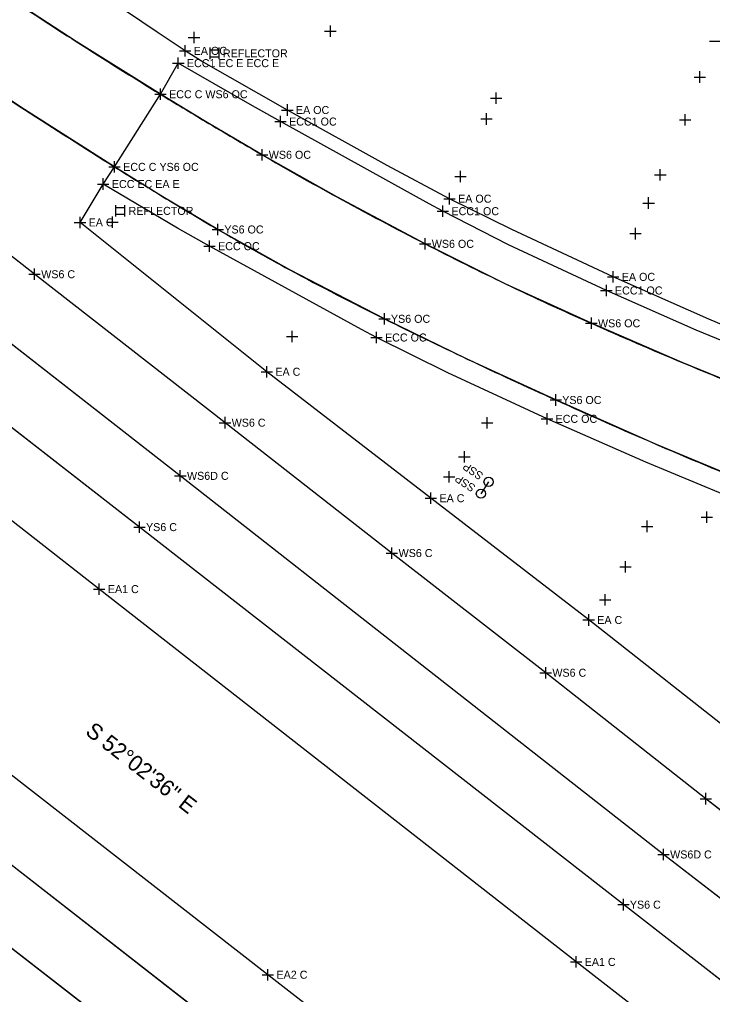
# Model space of a CAD drawing. Extents: x 1324236 to 1326110, y 459090 to 460782.
# Drawn here: x 1324542.9 to 1324664.1, y 460451 to 460621.6 of the extents above; entities that cross this region are included whole.
import ezdxf

# ---------------------------------------------------------------- set-up
doc = ezdxf.new("R2010")
doc.units = 0
for name, color, linetype in [('BD_X_Canopy', 7, 'Continuous'), ('DR_X_Ditch', 7, 'Continuous'), ('DT_X_Contour_Minor', 7, 'Continuous'), ('DT_X_Terrain_Ground_Line', 7, 'Continuous'), ('DV_X_Property_Line', 7, 'Continuous'), ('PM_X_Edge_Line', 7, 'Continuous'), ('PM_X_Lane_Line', 7, 'Continuous'), ('PV_X_Shoulder', 7, 'Continuous'), ('RW_X_CL', 7, 'Continuous'), ('RW_X_Esmt_SH', 7, 'Continuous')]:
    doc.layers.add(name, color=color, linetype=linetype)

msp = doc.modelspace()

# ---------------------------------------------------------------- linework, layer by layer
at = {"layer": 'BD_X_Canopy'}
for points in [[(1324899.46, 460285.8), (1324816.32, 460350.02), (1324738, 460411.76), (1324655.48, 460475.52), (1324571, 460541.76), (1324483.76, 460609.87), (1324398.74, 460676.2), (1324371.29, 460697.8)], [(1324658.11, 460368.1), (1324570.73, 460436.38), (1324490.36, 460498.76), (1324409.95, 460562.12), (1324331.06, 460623.37)]]:
    msp.add_lwpolyline(points, dxfattribs=at)
at = {"layer": 'DR_X_Ditch'}
for points in [[(1324878.81, 460316.8), (1324851.22, 460338.14), (1324823.13, 460360.06), (1324797.18, 460380.62), (1324771.19, 460400.89), (1324745.05, 460421.13), (1324717.74, 460442.29), (1324690.08, 460463.98), (1324662.89, 460485.28), (1324634.89, 460507.31), (1324608, 460528.25), (1324578.82, 460551.06), (1324545.51, 460577.03), (1324519.35, 460597.5), (1324491.34, 460619.11), (1324462.72, 460641.59), (1324434.69, 460663.56), (1324406.17, 460685.88), (1324379.47, 460706.64)], [(1324891.6, 460277.31), (1324809.63, 460340.84), (1324730.77, 460402.67), (1324648.48, 460466.74), (1324563.88, 460532.79), (1324477.11, 460600.29), (1324390.8, 460667.51), (1324364.85, 460687.72)], [(1324662.39, 460379.05), (1324578.69, 460444.65), (1324497.47, 460507.91), (1324417.96, 460569.9), (1324337.82, 460632.62)], [(1324672.91, 460555.83), (1324658.73, 460561.61), (1324658.73, 460561.61), (1324642.88, 460568.45), (1324642.88, 460568.45), (1324627.95, 460575.32), (1324627.95, 460575.32), (1324613.8, 460582.35), (1324613.8, 460582.35), (1324598.37, 460590.55), (1324598.37, 460590.55), (1324585.3, 460597.93), (1324585.3, 460597.93), (1324575.38, 460603.77), (1324575.38, 460603.77), (1324567.54, 460608.52), (1324567.54, 460608.52), (1324552.81, 460617.74), (1324552.81, 460617.74), (1324540.09, 460626.06)], [(1324667.15, 460541.87), (1324654.26, 460547.26), (1324654.26, 460547.26), (1324636.66, 460555.03), (1324636.66, 460555.03), (1324621.17, 460562.19), (1324621.17, 460562.19), (1324606.7, 460569.23), (1324606.7, 460569.23), (1324590.14, 460577.8), (1324590.14, 460577.8), (1324577.57, 460584.86), (1324577.57, 460584.86), (1324567.95, 460590.6), (1324567.95, 460590.6), (1324559.51, 460595.81), (1324559.51, 460595.81), (1324543.75, 460605.86), (1324543.75, 460605.86), (1324531.79, 460613.74)]]:
    msp.add_lwpolyline(points, dxfattribs=at)
at = {"layer": 'DT_X_Contour_Minor'}
msp.add_line((1324624.9, 460540.71), (1324623.56, 460538.64), dxfattribs=at)
for centre in [(1324624.9, 460540.71), (1324623.56, 460538.64)]:
    msp.add_circle(centre, 0.8, dxfattribs=at)
at = {"layer": 'DT_X_Terrain_Ground_Line'}
for p, q in [((1324576.15, 460616.68), (1324576.15, 460614.68)), ((1324577.75, 460616.68), (1324577.75, 460614.68)), ((1324576.15, 460616.28), (1324577.75, 460616.28)), ((1324576.15, 460615.08), (1324577.75, 460615.08)), ((1324559.66, 460589.12), (1324559.66, 460587.12)), ((1324559.66, 460588.72), (1324561.26, 460588.72)), ((1324561.26, 460589.12), (1324561.26, 460587.12)), ((1324559.66, 460587.52), (1324561.26, 460587.52))]:
    msp.add_line(p, q, dxfattribs=at)
at = {"layer": 'DV_X_Property_Line'}
for p, q in [((1324571.84, 460615.11), (1324571.84, 460617.11)), ((1324570.65, 460612.96), (1324570.65, 460614.96)), ((1324570.84, 460616.11), (1324572.84, 460616.11)), ((1324569.65, 460613.96), (1324571.65, 460613.96)), ((1324566.54, 460608.52), (1324568.54, 460608.52)), ((1324567.54, 460607.52), (1324567.54, 460609.52)), ((1324589.72, 460604.76), (1324589.72, 460606.76)), ((1324588.52, 460602.74), (1324588.52, 460604.74)), ((1324588.72, 460605.76), (1324590.72, 460605.76)), ((1324587.52, 460603.74), (1324589.52, 460603.74)), ((1324559.51, 460594.81), (1324559.51, 460596.81)), ((1324558.51, 460595.81), (1324560.51, 460595.81)), ((1324556.53, 460592.81), (1324558.53, 460592.81)), ((1324557.53, 460591.81), (1324557.53, 460593.81)), ((1324618.08, 460589.25), (1324618.08, 460591.25)), ((1324617.08, 460590.25), (1324619.08, 460590.25)), ((1324615.91, 460588.06), (1324617.91, 460588.06)), ((1324616.91, 460587.06), (1324616.91, 460589.06)), ((1324552.47, 460586.1), (1324554.47, 460586.1)), ((1324553.47, 460585.1), (1324553.47, 460587.1)), ((1324576.1, 460580.94), (1324576.1, 460582.94)), ((1324575.1, 460581.94), (1324577.1, 460581.94)), ((1324646.7, 460575.57), (1324646.7, 460577.57)), ((1324645.7, 460576.57), (1324647.7, 460576.57)), ((1324644.5, 460574.19), (1324646.5, 460574.19)), ((1324645.5, 460573.19), (1324645.5, 460575.19)), ((1324604.3, 460565.96), (1324606.3, 460565.96)), ((1324605.3, 460564.96), (1324605.3, 460566.96)), ((1324586.12, 460558.97), (1324586.12, 460560.97)), ((1324585.12, 460559.97), (1324587.12, 460559.97)), ((1324635.12, 460550.73), (1324635.12, 460552.73)), ((1324634.12, 460551.73), (1324636.12, 460551.73)), ((1324614.82, 460536.84), (1324614.82, 460538.84)), ((1324613.82, 460537.84), (1324615.82, 460537.84)), ((1324556.83, 460520.94), (1324556.83, 460522.94)), ((1324555.83, 460521.94), (1324557.83, 460521.94)), ((1324641.41, 460516.54), (1324643.41, 460516.54)), ((1324642.41, 460515.54), (1324642.41, 460517.54)), ((1324639.21, 460456.72), (1324641.21, 460456.72)), ((1324640.21, 460455.72), (1324640.21, 460457.72)), ((1324586.32, 460453.48), (1324586.32, 460455.48)), ((1324585.32, 460454.48), (1324587.32, 460454.48))]:
    msp.add_line(p, q, dxfattribs=at)
at = {"layer": 'PM_X_Edge_Line'}
for p, q in [((1324563.88, 460532.79), (1324477.11, 460600.29)), ((1324545.51, 460577.03), (1324519.35, 460597.5)), ((1324578.82, 460551.06), (1324545.51, 460577.03)), ((1324608, 460528.25), (1324578.82, 460551.06)), ((1324648.48, 460466.74), (1324563.88, 460532.79)), ((1324634.89, 460507.31), (1324608, 460528.25)), ((1324578.69, 460444.65), (1324497.47, 460507.91)), ((1324662.89, 460485.28), (1324634.89, 460507.31)), ((1324690.08, 460463.98), (1324662.89, 460485.28)), ((1324730.77, 460402.67), (1324648.48, 460466.74))]:
    msp.add_line(p, q, dxfattribs=at)
for centre, radius, start, end in [((1324943.63, 461229.32), 725.79, 236.22039, 237.41995), ((1325064.03, 461417.73), 949.39, 237.41995, 238.46878), ((1325011.24, 461328.92), 861.03, 236.1628, 237.11609), ((1324946.21, 461225.7), 724.09, 238.46878, 239.19407), ((1325339.11, 461836.05), 1464.91, 237.11609, 237.84694), ((1325160.76, 461585.52), 1143.02, 239.19407, 239.77135), ((1324859.73, 461068.9), 545.1, 239.7713, 241.3488), ((1324887.88, 461118.21), 617.03, 237.84694, 238.76857), ((1324975.5, 461262.71), 786.02, 238.76857, 239.58514), ((1324952.69, 461239.04), 738.97, 241.34884, 242.70367), ((1324767.55, 460908.48), 375.26, 239.5851, 241.7857), ((1324853.38, 461046.6), 522.42, 242.7037, 244.4367), ((1324887.22, 461131.53), 628.39, 241.78566, 243.48612), ((1324871.6, 461084.68), 564.64, 244.4367, 246.1037), ((1324965.93, 461289.29), 804.69, 243.48612, 244.63192), ((1325003.45, 461382.26), 890.12, 246.10372, 247.21496), ((1325008.67, 461379.44), 904.46, 244.63192, 245.71269), ((1324930.04, 461207.51), 700.57, 247.21496, 248.46754), ((1325115.94, 461617.15), 1165.25, 245.71269, 246.65873), ((1324897.65, 461111.3), 614.32, 246.65873, 247.96167)]:
    msp.add_arc(centre, radius, start, end, dxfattribs=at)
at = {"layer": 'PM_X_Lane_Line'}
for p, q in [((1324571, 460541.76), (1324483.76, 460609.87)), ((1324655.48, 460475.52), (1324571, 460541.76)), ((1324570.73, 460436.38), (1324490.36, 460498.76)), ((1324738, 460411.76), (1324655.48, 460475.52))]:
    msp.add_line(p, q, dxfattribs=at)
at = {"layer": 'PV_X_Shoulder'}
for points in [[(1324884.45, 460266.49), (1324856.61, 460288.28), (1324829.47, 460309.8), (1324801.93, 460331.35), (1324773.75, 460352.98), (1324722.57, 460392.66), (1324640.21, 460456.72), (1324556.83, 460521.94), (1324468.66, 460590.9), (1324383.42, 460657.59), (1324356.31, 460678.35)], [(1324892.37, 460493.49), (1324860.6, 460503.39), (1324828.49, 460513.21), (1324798.71, 460522.26), (1324777.87, 460528.9), (1324767.13, 460532.33), (1324737.7, 460541.77), (1324736.57, 460542.13), (1324724.28, 460546.18), (1324705.87, 460552.49), (1324692.5, 460557.36), (1324676.12, 460563.81), (1324663.42, 460569.15), (1324646.7, 460576.57), (1324628.95, 460584.84), (1324618.08, 460590.25), (1324607.15, 460596.07), (1324589.72, 460605.76), (1324574.73, 460614.33), (1324571.84, 460616.11), (1324566.97, 460619.36), (1324545.31, 460634.03), (1324520.36, 460651)], [(1324669.98, 460389.31), (1324586.32, 460454.48), (1324504.97, 460517.77), (1324425.87, 460579.19), (1324344.79, 460642.38)], [(1324665.89, 460538.53), (1324652.43, 460544.13), (1324652.43, 460544.13), (1324635.12, 460551.73), (1324635.12, 460551.73), (1324617.77, 460559.76), (1324617.77, 460559.76), (1324605.3, 460565.96), (1324605.3, 460565.96), (1324602.68, 460567.36), (1324602.68, 460567.36), (1324576.1, 460581.94), (1324576.1, 460581.94), (1324570.51, 460585.11), (1324570.51, 460585.11), (1324557.53, 460592.81), (1324557.53, 460592.81), (1324559.51, 460595.81), (1324567.54, 460608.52), (1324570.65, 460613.96)], [(1324675.13, 460561.54), (1324661.23, 460567.27), (1324661.23, 460567.27), (1324645.5, 460574.19), (1324645.5, 460574.19), (1324628.41, 460582.2), (1324628.41, 460582.2), (1324616.91, 460588.06), (1324616.91, 460588.06), (1324614.53, 460589.36), (1324614.53, 460589.36), (1324588.52, 460603.74), (1324588.52, 460603.74), (1324583.21, 460606.73), (1324583.21, 460606.73), (1324570.65, 460613.96), (1324570.65, 460613.96)], [(1324886.1, 460326.42), (1324858.75, 460347.83), (1324830.89, 460369.39), (1324804.09, 460390.5), (1324778.12, 460410.62), (1324752.25, 460430.86), (1324725.08, 460452.05), (1324697.48, 460473.35), (1324670.11, 460494.77), (1324642.41, 460516.54), (1324614.82, 460537.84), (1324586.12, 460559.97), (1324553.47, 460586.1), (1324557.53, 460592.81)]]:
    msp.add_lwpolyline(points, dxfattribs=at)
at = {"layer": 'RW_X_CL'}
for p, q in [((1324597.24, 460618.56), (1324597.24, 460620.56)), ((1324572.4, 460618.43), (1324574.4, 460618.43)), ((1324573.4, 460617.43), (1324573.4, 460619.43)), ((1324596.24, 460619.56), (1324598.24, 460619.56)), ((1324663.54, 460617.78), (1324665.54, 460617.78)), ((1324660.83, 460611.53), (1324662.83, 460611.53)), ((1324661.83, 460610.53), (1324661.83, 460612.53)), ((1324626.23, 460606.82), (1324626.23, 460608.82)), ((1324625.23, 460607.82), (1324627.23, 460607.82)), ((1324624.53, 460603.19), (1324624.53, 460605.19)), ((1324659.28, 460603.06), (1324659.28, 460605.06)), ((1324623.53, 460604.19), (1324625.53, 460604.19)), ((1324658.28, 460604.06), (1324660.28, 460604.06)), ((1324584.3, 460597.93), (1324586.3, 460597.93)), ((1324585.3, 460596.93), (1324585.3, 460598.93)), ((1324619.98, 460593.13), (1324619.98, 460595.13)), ((1324654.93, 460593.43), (1324654.93, 460595.43)), ((1324618.98, 460594.13), (1324620.98, 460594.13)), ((1324653.93, 460594.43), (1324655.93, 460594.43)), ((1324651.89, 460589.49), (1324653.89, 460589.49)), ((1324652.89, 460588.49), (1324652.89, 460590.49)), ((1324558.14, 460586.16), (1324560.14, 460586.16)), ((1324559.14, 460585.16), (1324559.14, 460587.16)), ((1324576.57, 460584.86), (1324578.57, 460584.86)), ((1324577.57, 460583.86), (1324577.57, 460585.86)), ((1324650.6, 460583.13), (1324650.6, 460585.13)), ((1324613.8, 460581.35), (1324613.8, 460583.35)), ((1324649.6, 460584.13), (1324651.6, 460584.13)), ((1324612.8, 460582.35), (1324614.8, 460582.35)), ((1324545.51, 460576.03), (1324545.51, 460578.03)), ((1324544.51, 460577.03), (1324546.51, 460577.03)), ((1324605.7, 460569.23), (1324607.7, 460569.23)), ((1324606.7, 460568.23), (1324606.7, 460570.23)), ((1324642.88, 460567.45), (1324642.88, 460569.45)), ((1324641.88, 460568.45), (1324643.88, 460568.45)), ((1324589.55, 460566.14), (1324591.55, 460566.14)), ((1324590.55, 460565.14), (1324590.55, 460567.14)), ((1324636.66, 460554.03), (1324636.66, 460556.03)), ((1324635.66, 460555.03), (1324637.66, 460555.03)), ((1324578.82, 460550.06), (1324578.82, 460552.06)), ((1324624.65, 460550.02), (1324624.65, 460552.02)), ((1324577.82, 460551.06), (1324579.82, 460551.06)), ((1324623.65, 460551.02), (1324625.65, 460551.02)), ((1324619.67, 460545.1), (1324621.67, 460545.1)), ((1324620.67, 460544.1), (1324620.67, 460546.1)), ((1324570, 460541.76), (1324572, 460541.76)), ((1324571, 460540.76), (1324571, 460542.76)), ((1324617.03, 460541.6), (1324619.03, 460541.6)), ((1324618.03, 460540.6), (1324618.03, 460542.6)), ((1324663.05, 460533.54), (1324663.05, 460535.54)), ((1324563.88, 460531.79), (1324563.88, 460533.79)), ((1324652.63, 460531.92), (1324652.63, 460533.92)), ((1324662.05, 460534.54), (1324664.05, 460534.54)), ((1324562.88, 460532.79), (1324564.88, 460532.79)), ((1324651.63, 460532.92), (1324653.63, 460532.92)), ((1324607, 460528.25), (1324609, 460528.25)), ((1324608, 460527.25), (1324608, 460529.25)), ((1324648.83, 460524.85), (1324648.83, 460526.85)), ((1324647.83, 460525.85), (1324649.83, 460525.85)), ((1324644.31, 460520.08), (1324646.31, 460520.08)), ((1324645.31, 460519.08), (1324645.31, 460521.08)), ((1324634.89, 460506.31), (1324634.89, 460508.31)), ((1324633.89, 460507.31), (1324635.89, 460507.31)), ((1324661.89, 460485.28), (1324663.89, 460485.28)), ((1324662.89, 460484.28), (1324662.89, 460486.28)), ((1324654.48, 460475.52), (1324656.48, 460475.52)), ((1324655.48, 460474.52), (1324655.48, 460476.52)), ((1324647.48, 460466.74), (1324649.48, 460466.74)), ((1324648.48, 460465.74), (1324648.48, 460467.74))]:
    msp.add_line(p, q, dxfattribs=at)

# ---------------------------------------------------------------- texts
at = {"layer": 'DT_X_Contour_Minor'}
for rotation, p in [(145.6281, (1324624.1, 460542.1)), (146.7178, (1324622.74, 460540.02))]:
    msp.add_text('SSP', height=1.4, rotation=rotation, dxfattribs=at).set_placement(p)
at = {"layer": 'DV_X_Property_Line'}
for s, p in [('EA OC', (1324573.34, 460615.41)), ('ECC1 EC E ECC E', (1324572.15, 460613.26)), ('ECC C WS6 OC', (1324569.04, 460607.82)), ('EA OC', (1324591.22, 460605.06)), ('ECC1 OC', (1324590.02, 460603.04)), ('ECC C YS6 OC', (1324561.01, 460595.11)), ('ECC EC EA E', (1324559.03, 460592.11)), ('EA OC', (1324619.58, 460589.55)), ('ECC1 OC', (1324618.41, 460587.36)), ('EA C', (1324554.97, 460585.4)), ('ECC OC', (1324577.6, 460581.24)), ('EA OC', (1324648.2, 460575.87)), ('ECC1 OC', (1324647, 460573.49)), ('ECC OC', (1324606.8, 460565.26)), ('EA C', (1324587.62, 460559.27)), ('ECC OC', (1324636.62, 460551.03)), ('EA C', (1324616.32, 460537.14)), ('EA1 C', (1324558.33, 460521.24)), ('EA C', (1324643.91, 460515.84)), ('EA1 C', (1324641.71, 460456.02)), ('EA2 C', (1324587.82, 460453.78))]:
    msp.add_text(s, height=1.4, dxfattribs=at).set_placement(p)
at = {"layer": 'PM_X_Lane_Line'}
msp.add_text('S 52°02\'36" E', height=2.8, rotation=322.0433, dxfattribs=at).set_placement((1324554.22, 460496.67))
at = {"layer": 'RW_X_CL'}
for s, p in [('WS6 OC', (1324586.47, 460597.23)), ('YS6 OC', (1324578.7, 460584.16)), ('WS6 OC', (1324614.97, 460581.65)), ('WS6 C', (1324546.68, 460576.33)), ('YS6 OC', (1324607.83, 460568.53)), ('WS6 OC', (1324644.04, 460567.75)), ('YS6 OC', (1324637.78, 460554.33)), ('WS6 C', (1324579.98, 460550.36)), ('WS6D C', (1324572.17, 460541.06)), ('YS6 C', (1324565.01, 460532.09)), ('WS6 C', (1324609.17, 460527.55)), ('WS6 C', (1324636.06, 460506.61)), ('WS6D C', (1324656.65, 460474.82)), ('YS6 C', (1324649.61, 460466.04))]:
    msp.add_text(s, height=1.4, dxfattribs=at).set_placement(p)
at = {"layer": 'RW_X_Esmt_SH'}
for p in [(1324578.45, 460614.98), (1324561.96, 460587.42)]:
    msp.add_text('REFLECTOR', height=1.4, dxfattribs=at).set_placement(p)

doc.saveas('drawing.dxf')
